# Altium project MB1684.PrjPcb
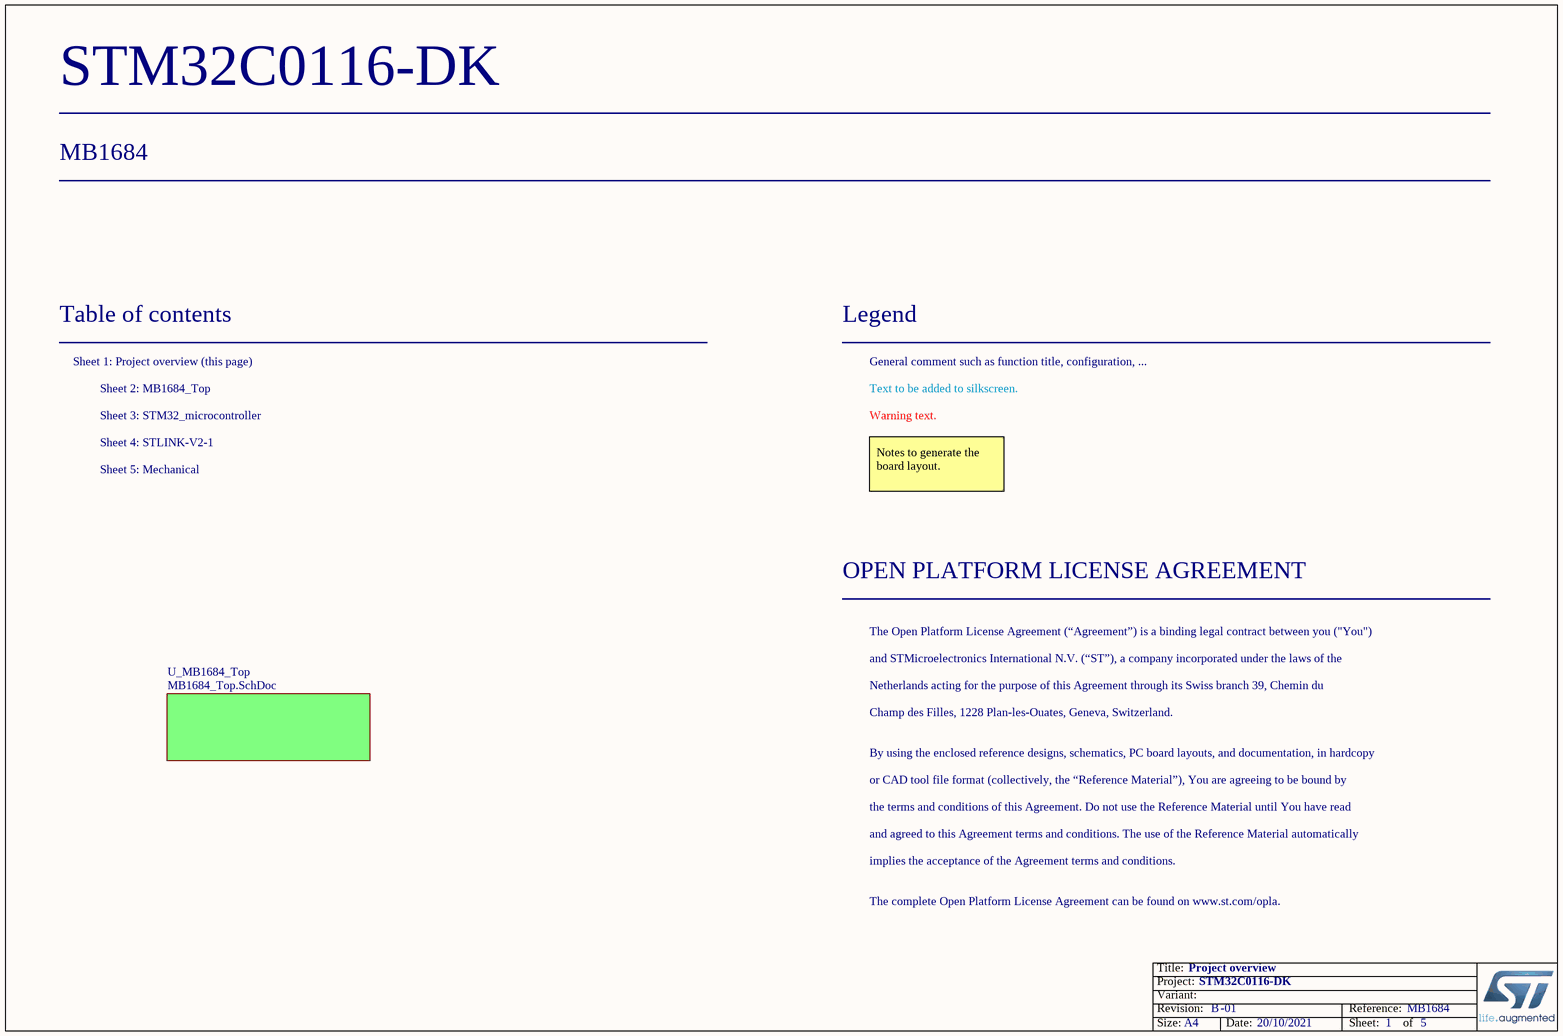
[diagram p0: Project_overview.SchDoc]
Board_Reference: MB1684; Board_PCB_Revision: B; Board_Name: STM32C0116-DK; Board_Document_Date: 20/10/2021; Board_Assembly_Revision: 01
5 sheets, 73 parts. Net scope: flat (ports and power ports of the same name join across sheets).
Board file: MB1684.PcbDoc
Sheets:
  Project_overview.SchDoc
    U_MB1684_Top = MB1684_Top.SchDoc
      U_STM32_microcontroller = STM32_microcontroller.SchDoc
      U_ST_LINK_V2_1 = ST_LINK_V2_1.SCHDOC
      U_Mechanical = Mechanical.SchDoc

## Sheet Project_overview.SchDoc: Project overview
size A4; Date: Not used; ApprovedBy: Not used; CheckedBy: Not used; Author: Not used; CompanyName: STMicroelectronics; DrawnBy: Not used; Engineer: Not used; Organization: Not used; Address1: Not used; Address2: Not used; Address3: Not used; Address4: Not used; DocumentNumber: Not used; Revision: Not used; SheetNumber: 1; SheetTotal: 5

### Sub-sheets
U_MB1684_Top = MB1684_Top.SchDoc: no entries

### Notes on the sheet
- Table of contents
- Sheet 1: Project overview (this page)
- Legend
- General comment such as function title, configuration, ...
- Sheet 2: MB1684_Top
- Sheet 4: STLINK-V2-1
- Sheet 3: STM32_microcontroller
- Text to be added to silkscreen.
- Warning text.
- Sheet 5: Mechanical
- Notes to generate the board layout.
- OPEN PLATFORM LICENSE AGREEMENT
- The Open Platform License Agreement (“Agreement”) is a binding legal contract between you ("You")
- and STMicroelectronics International N.V. (“ST”), a company incorporated under the laws of the
- Netherlands acting for the purpose of this Agreement through its Swiss branch 39, Chemin du
- Champ des Filles, 1228 Plan-les-Ouates, Geneva, Switzerland.
- By using the enclosed reference designs, schematics, PC board layouts, and documentation, in hardcopy
- or CAD tool file format (collectively, the “Reference Material”), You are agreeing to be bound by
- the terms and conditions of this Agreement. Do not use the Reference Material until You have read
- and agreed to this Agreement terms and conditions. The use of the Reference Material automatically
- implies the acceptance of the Agreement terms and conditions.
- The complete Open Platform License Agreement can be found on www.st.com/opla.

## Sheet MB1684_Top.SchDoc: Top hierarchical view
size A4; Date: Not used; ApprovedBy: Not used; CheckedBy: Not used; Author: Not used; CompanyName: STMicroelectronics; DrawnBy: Not used; Engineer: Not used; Organization: Not used; Address1: Not used; Address2: Not used; Address3: Not used; Address4: Not used; DocumentNumber: Not used; Revision: A-01-P3; SheetNumber: 2; SheetTotal: 5
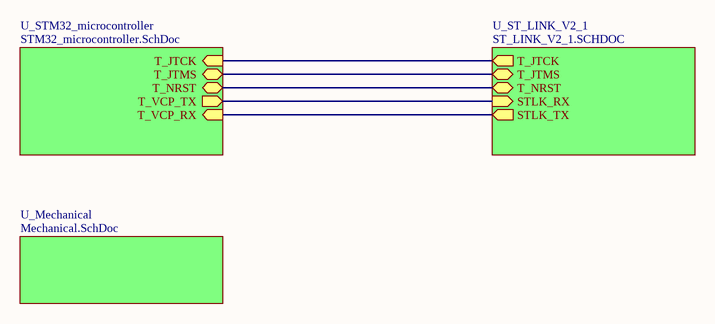
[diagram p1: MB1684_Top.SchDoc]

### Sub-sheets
U_Mechanical = Mechanical.SchDoc: no entries
U_ST_LINK_V2_1 = ST_LINK_V2_1.SCHDOC: T_JTMS (bidir), T_JTCK (out), T_NRST (bidir), STLK_RX (in), STLK_TX (out)
U_STM32_microcontroller = STM32_microcontroller.SchDoc: T_JTMS (bidir), T_NRST (bidir), T_JTCK (in), T_VCP_RX (in), T_VCP_TX (out)

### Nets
(unnamed): sheet U_STM32_microcontroller/T_JTMS, sheet U_ST_LINK_V2_1/T_JTMS
(unnamed): sheet U_STM32_microcontroller/T_NRST, sheet U_ST_LINK_V2_1/T_NRST  [a separate net that carries the same name]
(unnamed): sheet U_STM32_microcontroller/T_JTCK, sheet U_ST_LINK_V2_1/T_JTCK  [a separate net that carries the same name]
(unnamed): sheet U_STM32_microcontroller/T_VCP_RX, sheet U_ST_LINK_V2_1/STLK_TX  [a separate net that carries the same name]
(unnamed): sheet U_STM32_microcontroller/T_VCP_TX, sheet U_ST_LINK_V2_1/STLK_RX  [a separate net that carries the same name]

## Sheet STM32_microcontroller.SchDoc: MCU
size A4; CompanyName: STMicroelectronics; Organization: Microcontrollers Division; DocumentNumber: MCD16-037; Revision: A-01; SheetNumber: 3; SheetTotal: 5; Project: STM32L476 Brisk
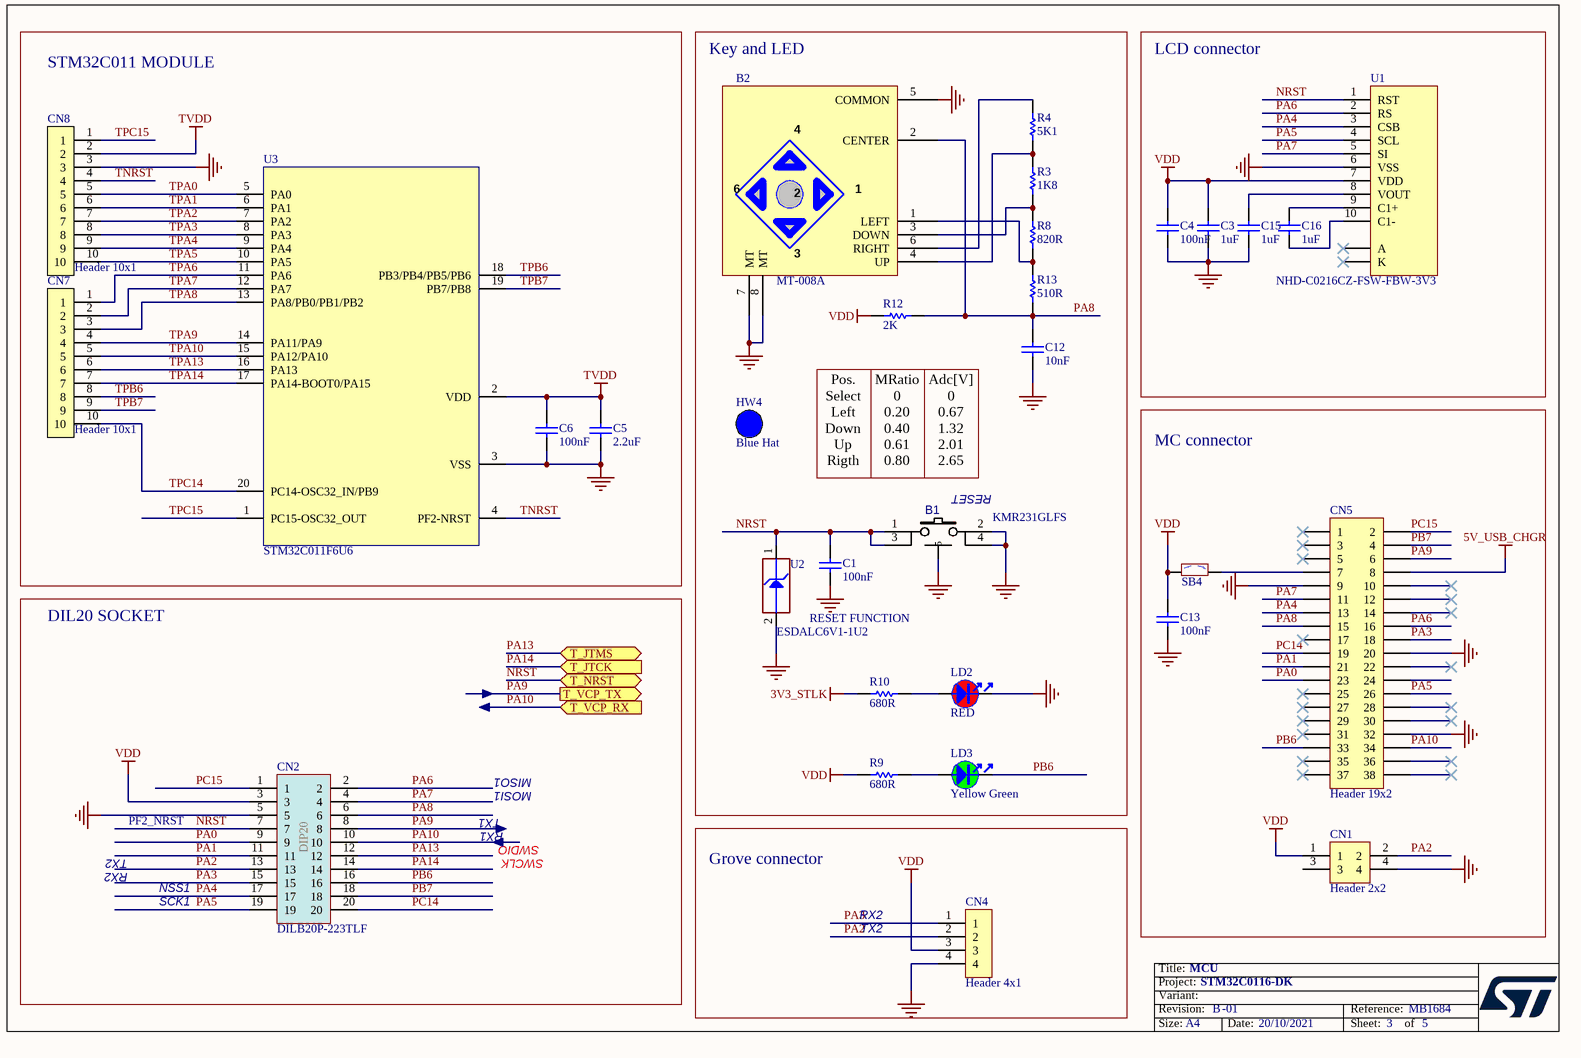
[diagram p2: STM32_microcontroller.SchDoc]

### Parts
B1  value KMR231GLFS  [SWI_C&K_Y78B23110FP__ITT_KMR231GLFS]  (hidden comment: SW-PUSH-CMS_KMR2_BLACK)
B2  value MT-008A  [SWI_XIEJIA_MT-008A_6P]  (hidden comment: Joystick MT-008A_M)
C1  value 100nF  [C0402]  (hidden comment: Capacitor)
C3  value 1uF  [C0603]  (hidden comment: Capacitor)
C4  value 100nF  [C0402]  (hidden comment: Capacitor)
C5  value 2.2uF  [C0603]  (hidden comment: Capacitor)
C6  value 100nF  [C0402]  (hidden comment: Capacitor)
C12  value 10nF  [C0402]  (hidden comment: Capacitor)
C13  value 100nF  [C0402]  (hidden comment: Capacitor)
C15  value 1uF  [C0603]  (hidden comment: Capacitor)
C16  value 1uF  [C0603]  (hidden comment: Capacitor)
CN1  Header 2x2  [CON_SAMTEC_TSW-102-09-G-D]
CN2  value DILB20P-223TLF  [CON_FCI_DILB20P-223TLF]  (hidden comment: Socket 10x2_DIP20)
CN4  Header 4x1  [CON_988-JIUBABA_A2006LF-04A]
CN5  Header 19x2  [CON_SAMTEC_TSW-119-09-X-D]
CN7  Header 10x1  [CON_SAMTEC_TSW-110-07-G-S]
CN8  Header 10x1  [CON_SAMTEC_TSW-110-07-G-S]
HW4  value Blue Hat  (hidden comment: BUTTON_HAT_BLUE)  (mechanical)
LD2  value RED  [LED_0402_KINGBRIGHT_KPHHS-1005SURCK_HYPER-RED_1A2K_H0P5]  (hidden comment: LED_red)
LD3  value Yellow Green  [LED_0402_EVERLIGHT_16-213SYGC/S530-E3-TR8 _YELLOW-GREEN_1A2K_H0P45]  (hidden comment: LED_green)
R3  value 1K8  [R0402]  (hidden comment: Resistor)
R4  value 5K1  [R0402]  (hidden comment: Resistor)
R8  value 820R  [R0402]  (hidden comment: Resistor)
R9  value 680R  [R0402]  (hidden comment: Resistor)
R10  value 680R  [R0402]  (hidden comment: Resistor)
R12  value 2K  [R0402]  (hidden comment: Resistor)
R13  value 510R  [R0402]  (hidden comment: Resistor)
SB4  SB_OFF  [SOLDER-BRIDGE_R0603-0R]  (value not drawn)
U1  NHD-C0216CZ-FSW-FBW-3V3  [LCD_NHD_C0216CZ_FSW_FBW_3V3]
U2  value ESDALC6V1-1U2  [ESD_ST0201]  (hidden comment: ESD-TRANSIL)
U3  STM32C011F6U6  [ICC_UFQFPN20_3X3_P050]

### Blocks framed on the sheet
STM32C011 MODULE: C5 C6 CN7 CN8 U3
Key and LED: B1 B2 C1 C12 HW4 LD2 LD3 R3 R4 R8-R10 R12 R13 U2
LCD connector: C3 C4 C15 C16 U1
MC connector: C13 CN1 CN5 SB4
DIL20 SOCKET: CN2
Grove connector: CN4

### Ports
T_JTCK (in), T_JTMS (bidir), T_NRST (bidir), T_VCP_RX (in), T_VCP_TX (out)

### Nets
3V3_STLK: R10.2
5V_USB_CHGR: CN5.8
GND: B1.2 B1.4 B1.5 B2.5(COMMON) B2.7(MT) B2.8(MT) C1.1 C3.1 C4.1 C12.1 C13.1 C15.1 CN1.4 CN2.5 CN4.4 CN5.9 CN5.20 CN5.32 LD2.2 U1.6(VSS) U2.2(GND)
TGND: C5.1 C6.1 CN8.3 U3.3(VSS)
TVDD: C5.2 C6.2 CN8.2 U3.2(VDD)
VDD: C3.2 C4.2 C13.2 CN1.1 CN2.3 CN4.3 R9.2 R12.1 SB4.1 U1.7(VDD)
NRST: B1.1 B1.3 C1.2 CN2.7 U1.1(RST) U2.1(IO1) ; port T_NRST
PA0: CN2.9 CN5.23
PA1: CN2.11 CN5.21
PA2: CN1.2 CN2.13 CN4.2
PA3: CN2.15 CN4.1 CN5.18
PA4: CN2.17 CN5.13 U1.3(CSB)
PA5: CN2.19 CN5.26 U1.4(SCL)
PA6: CN2.2 CN5.16 U1.2(RS)
PA7: CN2.4 CN5.11 U1.5(SI)
PA8: B2.2(CENTER) C12.2 CN2.6 CN5.15 R12.2 R13.1
PA9: CN2.8 CN5.6 ; port T_VCP_TX
PA10: CN2.10 CN5.34 ; port T_VCP_RX
PA13: CN2.12 ; port T_JTMS
PA14: CN2.14 ; port T_JTCK
PB6: CN2.16 CN5.33 LD3.2
PB7: CN2.18 CN5.4
PC14: CN2.20 CN5.19
PC15: CN2.1 CN5.2
TNRST: CN8.4 U3.4(PF2-NRST)
TPA0: CN8.5 U3.5(PA0)
TPA1: CN8.6 U3.6(PA1)
TPA2: CN8.7 U3.7(PA2)
TPA3: CN8.8 U3.8(PA3)
TPA4: CN8.9 U3.9(PA4)
TPA5: CN8.10 U3.10(PA5)
TPA6: CN7.1 U3.11(PA6)
TPA7: CN7.2 U3.12(PA7)
TPA8: CN7.3 U3.13(PA8/PB0/PB1/PB2)
TPA9: CN7.4 U3.14(PA11/PA9)
TPA10: CN7.5 U3.15(PA12/PA10)
TPA13: CN7.6 U3.16(PA13)
TPA14: CN7.7 U3.17(PA14-BOOT0/PA15)
TPB6: CN7.8 U3.18(PB3/PB4/PB5/PB6)
TPB7: CN7.9 U3.19(PB7/PB8)
TPC14: CN7.10 U3.20(PC14-OSC32_IN/PB9)
TPC15: CN8.1 U3.1(PC15-OSC32_OUT)
NetB2_1: B2.1(LEFT) R8.1 R13.2
NetB2_3: B2.3(DOWN) R3.1 R8.2
NetB2_4: B2.4(UP) R3.2 R4.1
NetB2_6: B2.6(RIGHT) R4.2
NetC15_2: C15.2 U1.8(VOUT)
NetC16_1: C16.1 U1.10(C1-)
NetC16_2: C16.2 U1.9(C1+)
NetCN5_7: CN5.7 SB4.2
NetLD2_1: LD2.1 R10.1
NetLD3_1: LD3.1 R9.1

Not connected (* = marked no-connect by the designer): CN1 3; CN5 1* 3* 5* 10* 12* 14* 17* 22* 24 25* 27* 28* 29* 30* 31* 35* 36* 37* 38*; U1 11(A)* 12(K)*

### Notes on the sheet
- Pos.
  Select
  Left
  Down
  Up
  Rigth
- MRatio
  0
  0.20
  0.40
  0.61
  0.80
- Adc[V]
  0
  0.67
  1.32
  2.01
  2.65
- (near B1) RESET
- RESET FUNCTION
- MOSI1
- MISO1
- PF2_NRST
- TX2
- TX1
- RX1
- SWDIO
- SWCLK
- RX2
- NSS1
- SCK1

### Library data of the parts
B1 = MCD-01485: Microminiature Tact Switch for SMT - KMR 2 Series - 1.9 mm height; Part_Type: Misc; Manufacturer: C&K; Part_Preference: Recommended; Provided_By: SUBCO; Component_Country_Of_Origin: France
B2 = MCD-00132: Joystick, 4 dir, 1 OK; BMS_Part_Number: 9180124; Part_Preference: Recommended; Part_Type: Misc; Manufacturer: XIEJIA ELECTRONICS; Component_Country_Of_Origin: Unknown
C1 C4 C6 C13 = MCD-00006: Capacitor, MLCC, 100nF, 16V, X7R, +/-10%, 0402, T=0.5mm; Manufacturer_Part_Number: CC0402KRX7R7BB104; Manufacturer: YAGEO; Alternate_Manufacturer_Part_Number: GCM155R71C104KA55D; Alternate_Manufacturer: MURATA; Part_Preference: Recommended; Provided_By: SUBCO; ECCN_US: EAR99; ECCN_EU: NEC; Order_Code_RS: 616-9701; Component_Country_Of_Origin: China
C3 C15 C16 = MCD-01100: Capacitor, MLCC, 1uF, 25V, X5R, +/-10%, 0603, T=0.8mm; Manufacturer_Part_Number: CC0603KRX5R8BB105; Manufacturer: YAGEO; Alternate_Manufacturer_Part_Number: GCM155R71C104KA55D; Alternate_Manufacturer: MURATA; BMS_Part_Number: 9142279; Part_Preference: Recommended; ECCN_US: EAR99; ECCN_EU: NEC; Provided_By: SUBCO; Component_Country_Of_Origin: China
C5 = MCD-00654: Capacitor, MLCC, 2.2uF, 16V, X5R, +/-10%, 0603, T=0.8mm; Manufacturer_Part_Number: CC0603KRX5R7BB225; Manufacturer: YAGEO; Alternate_Manufacturer_Part_Number: GCM155R71C104KA55D; Alternate_Manufacturer: MURATA; BMS_Part_Number: 9142001; Part_Preference: Recommended; ECCN_US: EAR99; ECCN_EU: NEC; Provided_By: SUBCO; Component_Country_Of_Origin: China
C12 = MCD-00011: Capacitor, MLCC, 10nF, 16V, X7R, +/-10%, 0402, T=0.5mm; Manufacturer_Part_Number: CC0402KRX7R7BB103; Manufacturer: YAGEO; Alternate_Manufacturer_Part_Number: GCM155R71C104KA55D; Alternate_Manufacturer: MURATA; Part_Preference: Recommended; Provided_By: SUBCO; ECCN_US: EAR99; ECCN_EU: NEC; Order_Code_RS: 669-8688; Component_Country_Of_Origin: China
CN1 = MCD-02440: Header, 2x2, 2.54mm, VR, TH, T=5.84mm/10.16mm; Part_Type: Connector; Part_Preference: Recommended; Manufacturer: SAMTEC; Manufacturer_Part_Number: TSW-102-09-G-D; Component_Country_Of_Origin: China, Costa Rica, Malaysia, United States, Vietnam
CN2 = MCD-02204: Socket_IC, 20 (2 x 10) Pos DIP, 0.3" (7.62mm) Row Spacing Socket Tin Through Hole; Part_Preference: Recommended; Manufacturer: AMPHENOL ICC; Component_Country_Of_Origin: Taiwan
CN4 = MCD-01741: Header, 4x1, 2mm, VR, SMD; Part_Type: Connector; Manufacturer_Part_Number: A2006LF-04A; Manufacturer: JIUBABA; Part_Preference: Alternate; Component_Country_Of_Origin: Unknown; Alternate_EMS: A
CN5 = MCD-00213: Header, 19x2, 2.54mm, VR, TH, T=5.84mm/10.16mm; Manufacturer_Part_Number: TSW-119-09-G-D; Manufacturer: SAMTEC; Part_Type: Connector; Part_Preference: Recommended; Provided_By: SUBCO; Component_Country_Of_Origin: China, Costa Rica, Malaysia, United States, Vietnam
CN7 CN8 = MCD-02708: Header, 10x1, 2.54mm, VR, TH, T=5.84mm/2.54mm; Part_Type: Connector; Part_Preference: Recommended; Manufacturer: SAMTEC; Manufacturer_Part_Number: TSW-110-07-G-S
HW4 = MCD-02136: Switch hat, blue, For KTSC-62B; Part_Type: Misc; Part_Preference: Recommended; Manufacturer: APEM INC; Manufacturer_Part_Number: AKTSC62B; Order_Code_RS: 378-6779; Component_Country_Of_Origin: Unknown
LD2 = MCD-00708: LED 0402 Red; Part_Type: Display; Manufacturer_Part_Number: KPHHS-1005SURCK; Manufacturer: KINGBRIGHT; Alternate_Manufacturer_Part_Number: LS Q976-NR-1; Alternate_Manufacturer: OSRAM OPTO SEMICONDUCTORS; Part_Preference: Recommended; Provided_By: SUBCO; Component_Country_Of_Origin: Unknown
LD3 = MCD-02330: LED, Yellow Green, 2V, 25mA, 0402, 0.45mm; Part_Type: Display; Manufacturer_Part_Number: 16-213SYGC/S530-E3/TR8; Manufacturer: EVERLIGHT; Alternate_Manufacturer_Part_Number: LG Q396-PS-35; Alternate_Manufacturer: OSRAM OPTO SEMICONDUCTORS; Part_Preference: Recommended; Provided_By: SUBCO; Component_Country_Of_Origin: China
R3 = MCD-00409: Resistor, 1K8, 0402, +/-1%, 1/16W; Manufacturer_Part_Number: RC0402FR-071K8L; Manufacturer: YAGEO; Alternate_Manufacturer_Part_Number: RT0402FRE07100KL; Part_Preference: Recommended; ECCN_US: EAR99; ECCN_EU: NEC; Provided_By: SUBCO; Component_Country_Of_Origin: China
R4 = MCD-00333: Resistor, 5K1, 0402, +/-1%, 1/16W; Manufacturer_Part_Number: RC0402FR-075K1L; Manufacturer: YAGEO; Alternate_Manufacturer_Part_Number: RT0402FRE07100KL; Part_Preference: Recommended; ECCN_US: EAR99; ECCN_EU: NEC; Provided_By: SUBCO; Component_Country_Of_Origin: China
R8 = MCD-00527: Resistor, 820R, 0402, +/-1%, 1/16W; Manufacturer_Part_Number: RC0402FR-07820RL; Manufacturer: YAGEO; Alternate_Manufacturer_Part_Number: RT0402FRE07100KL; Part_Preference: Recommended; ECCN_US: EAR99; ECCN_EU: NEC; Provided_By: SUBCO; Component_Country_Of_Origin: China
R9 R10 = MCD-00507: Resistor, 680R, 0402, +/-1%, 1/16W; Manufacturer_Part_Number: RC0402FR-07680RL; Manufacturer: YAGEO; Alternate_Manufacturer_Part_Number: RT0402FRE07100KL; Part_Preference: Recommended; ECCN_US: EAR99; ECCN_EU: NEC; Provided_By: SUBCO; Component_Country_Of_Origin: China
R12 = MCD-00419: Resistor, 2K, 0402, +/-1%, 1/16W; Manufacturer_Part_Number: RC0402FR-072KL; Manufacturer: YAGEO; Alternate_Manufacturer_Part_Number: RT0402FRE07100KL; Part_Preference: Recommended; ECCN_US: EAR99; ECCN_EU: NEC; Provided_By: SUBCO; Component_Country_Of_Origin: China
R13 = MCD-00064: Resistor, 510R, 0402, +/-1%, 1/16W; Manufacturer_Part_Number: RC0402FR-07510RL; Manufacturer: YAGEO; Alternate_Manufacturer_Part_Number: RT0402FRE07100KL; Part_Preference: Recommended; ECCN_US: EAR99; ECCN_EU: NEC; Provided_By: SUBCO; Component_Country_Of_Origin: China
SB4 = MCD-00072: Solder Bridge OFF; Part_Type: Misc; Manufacturer_Part_Number: RC0603JR-070RL; Manufacturer: YAGEO; Part_Preference: Recommended; Component_Country_Of_Origin: China
U1 = MCD-02205: Character LCD Display Module Transflective 5 x 8 Dots FSTN - Film Super-Twisted Nematic LED - White Serial; Part_Preference: Recommended; Manufacturer: NEWHAVEN DISPLAY INTL; Component_Country_Of_Origin: China
U2 = MCD-00170: ESD protection 6V1; Part_Type: Diode; Manufacturer: STMICROELECTRONICS; BMS_Part_Number: 9151132; Part_Preference: Recommended; Manufacturer_HQ_COO: EU; Provided_By: SUBCO with ST control; ECCN_US: EAR99; ECCN_EU: NEC; Component_Country_Of_Origin: China
U3 = MCD-02313: MCU, ARM™-based 32-bit MCU Cortex-M0+, 32KB Flash, 6KB SRAM; Part_Type: IC; Part_Preference: Recommended; Manufacturer: STMICROELECTRONICS; Component_Country_Of_Origin: Unknown

## Sheet ST_LINK_V2_1.SCHDOC: ST-LINK/V2 SWD mode
size A4; CompanyName: STMicroelectronics; Organization: Microcontrollers Division; SheetNumber: 4; SheetTotal: 5
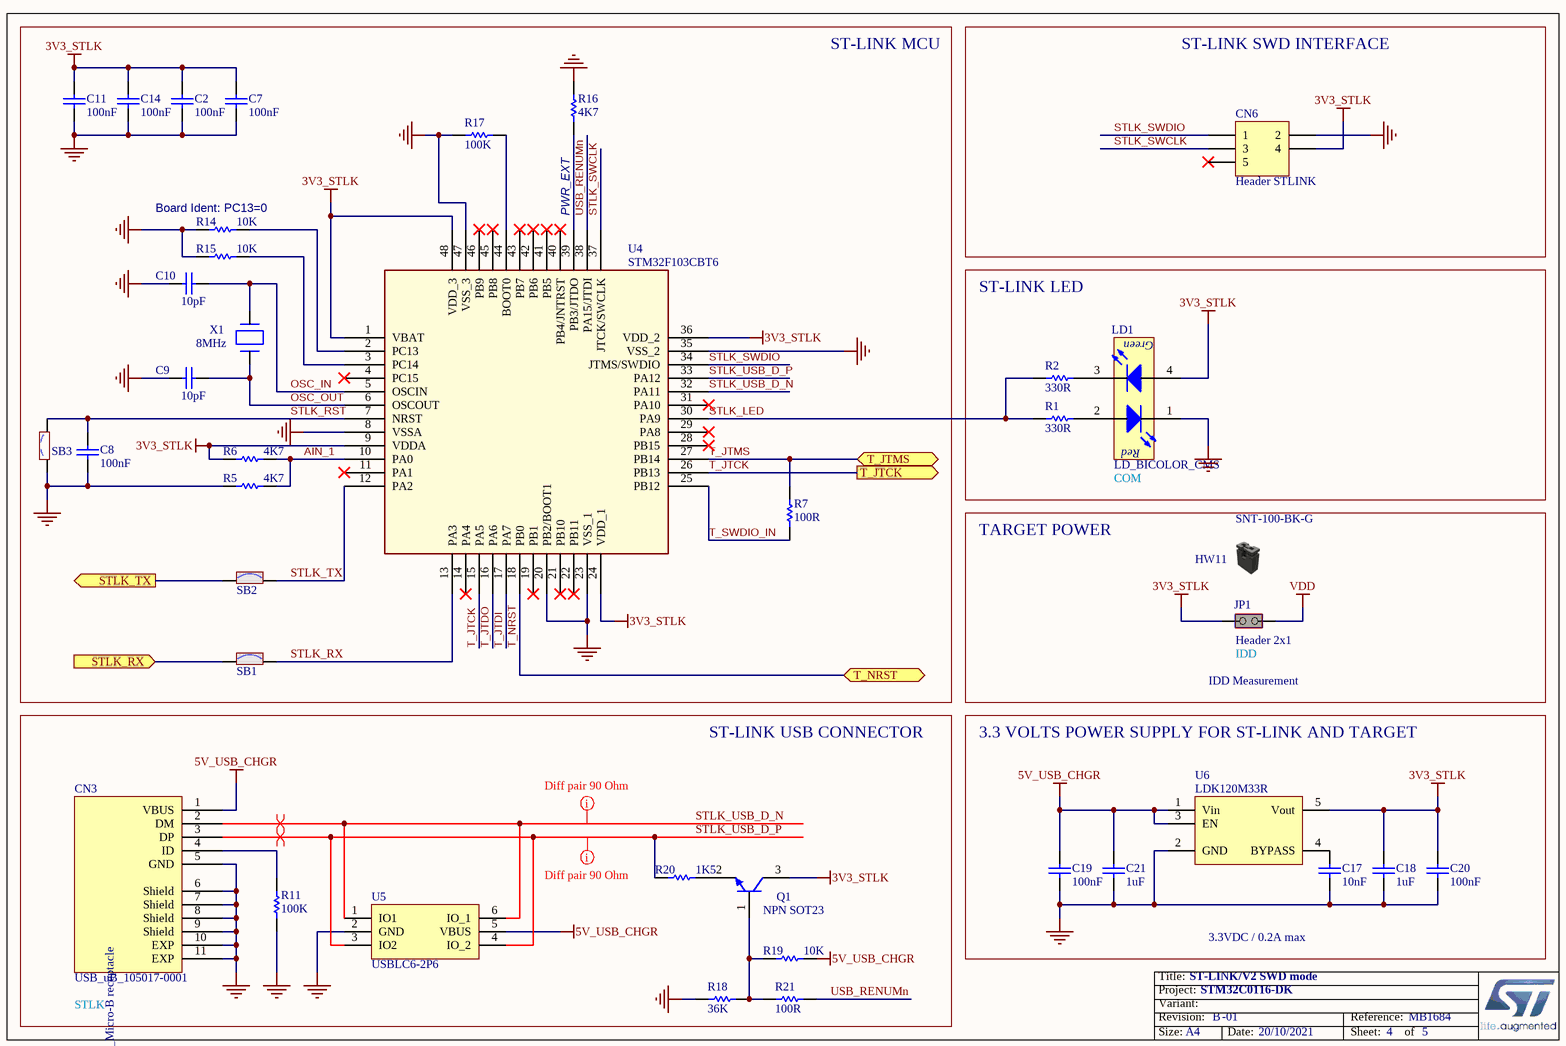
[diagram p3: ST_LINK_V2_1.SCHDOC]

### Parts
C2  value 100nF  [C0402]  (hidden comment: Capacitor)
C7  value 100nF  [C0402]  (hidden comment: Capacitor)
C8  value 100nF  [C0402]  (hidden comment: Capacitor)
C9  value 10pF  [C0402]  (hidden comment: Capacitor)
C10  value 10pF  [C0402]  (hidden comment: Capacitor)
C11  value 100nF  [C0402]  (hidden comment: Capacitor)
C14  value 100nF  [C0402]  (hidden comment: Capacitor)
C17  value 10nF  [C0402]  (hidden comment: Capacitor)
C18  value 1uF  [C0402]  (hidden comment: Capacitor)
C19  value 100nF  [C0402]  (hidden comment: Capacitor)
C20  value 100nF  [C0402]  (hidden comment: Capacitor)
C21  value 1uF  [C0402]  (hidden comment: Capacitor)
CN3  value USB_uB_105017-0001  [CON_USBMICROB_MOLEX_105017-0001_H2P90]  (hidden comment: USB_uB_105017.0001)
CN6  Header STLINK  [HDR_1x5_2R54_V_M]
HW11  value SNT-100-BK-G  (hidden comment: Shunt Black 2.54mm)  (mechanical)
JP1  value Header 2x1  [CON_SAMTEC_TSW-102-07-G-S]  (hidden comment: Jumper_Header 2x1 Fitted)
LD1  LD_BICOLOR_CMS  [LED_BI-GR_HSMF-A201-A00J1]
Q1  value NPN SOT23  [NPN_SOT23]  (hidden comment: 9013-SOT23)
R1  value 330R  [R0402]  (hidden comment: Resistor)
R2  value 330R  [R0402]  (hidden comment: Resistor)
R5  value 4K7  [R0402]  (hidden comment: Resistor)
R6  value 4K7  [R0402]  (hidden comment: Resistor)
R7  value 100R  [R0402]  (hidden comment: Resistor)
R11  value 100K  [R0402]  (hidden comment: Resistor)
R14  value 10K  [R0402]  (hidden comment: Resistor)
R15  value 10K  [R0402]  (hidden comment: Resistor)
R16  value 4K7  [R0402]  (hidden comment: Resistor)
R17  value 100K  [R0402]  (hidden comment: Resistor)
R18  value 36K  [R0402]  (hidden comment: Resistor)
R19  value 10K  [R0402]  (hidden comment: Resistor)
R20  value 1K5  [R0402]  (hidden comment: Resistor)
R21  value 100R  [R0402]  (hidden comment: Resistor)
SB1  SB_ON  [SOLDER-BRIDGE_R0402-0R]  (value not drawn)
SB2  SB_ON  [SOLDER-BRIDGE_R0402-0R]  (value not drawn)
SB3  SB_OFF  [SOLDER-BRIDGE_R0603-0R]  (value not drawn)
U4  STM32F103CBT6  [ICC_LQFP48_7X7_P050]
U5  USBLC6-2P6  [ESD_SOT666]
U6  LDK120M33R  [REG_SOT23-5L]
X1  value 8MHz  [CRY_NX3225GD_2P]  (hidden comment: XTAL_2_PINS)

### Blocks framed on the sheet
ST-LINK MCU: C2 C7-C11 C14 R5-R7 R14-R17 SB1-SB3 U4 X1
ST-LINK SWD INTERFACE: CN6
ST-LINK LED: LD1 R1 R2
TARGET POWER: HW11 JP1
ST-LINK USB CONNECTOR: CN3 Q1 R11 R18-R21 U5
3.3 VOLTS POWER SUPPLY FOR ST-LINK AND TARGET: C17-C21 U6

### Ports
STLK_RX (in), STLK_TX (out), T_JTCK (out), T_JTMS (bidir), T_NRST (bidir)

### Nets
3V3_STLK: C2.2 C7.2 C11.2 C14.2 C18.2 C20.2 CN6.4 JP1.1(COMMON) LD1.4(YellowGreen_anode) Q1.3(C) R6.1 U4.1(VBAT) U4.9(VDDA) U4.24(VDD_1) U4.36(VDD_2) U4.48(VDD_3) U6.5(Vout)
5V_USB_CHGR: C19.2 C21.2 CN3.1(VBUS) R19.2 U5.5(VBUS) U6.1(Vin) U6.3(EN)
GND: C2.1 C7.1 C8.1 C9.1 C10.1 C11.1 C14.1 C17.1 C18.1 C19.1 C20.1 C21.1 CN3.5(GND) CN3.6(Shield) CN3.7(Shield) CN3.8(Shield) CN3.9(Shield) CN3.10(EXP) CN3.11(EXP) CN6.2 LD1.1(RED_cathode) R5.1 R11.1 R14.1 R15.1 R16.2 R17.1 R18.1 SB3.1 U4.8(VSSA) U4.20(PB2/BOOT1) U4.23(VSS_1) U4.35(VSS_2) U4.47(VSS_3) U5.2(GND) U6.2(GND)
VDD: JP1.2(NO)
AIN_1: R5.2 R6.2 U4.10(PA0)
OSC_IN: C10.2 U4.5(OSCIN) X1.1(X1)
OSC_OUT: C9.2 U4.6(OSCOUT) X1.2(X2)
STLK_LED: R1.1 R2.1 U4.30(PA9)
STLK_RST: C8.2 SB3.2 U4.7(NRST)
STLK_RX: SB1.2 U4.13(PA3)
STLK_SWCLK: CN6.3 U4.37(JTCK/SWCLK)
STLK_SWDIO: CN6.1 U4.34(JTMS/SWDIO)
STLK_TX: SB2.2 U4.12(PA2)
STLK_USB_D_N: CN3.2(DM) U4.32(PA11) U5.1(IO1) U5.6(IO_1)
STLK_USB_D_P: CN3.3(DP) R20.1 U4.33(PA12) U5.3(IO2) U5.4(IO_2)
T_JTCK: U4.15(PA5) U4.26(PB13) ; port T_JTCK  [project net PA14]
T_JTDI: U4.17(PA7)
T_JTDO: U4.16(PA6)
T_JTMS: R7.2 U4.27(PB14) ; port T_JTMS  [project net PA13]
T_NRST: U4.18(PB0) ; port T_NRST  [project net NRST]
T_SWDIO_IN: R7.1 U4.25(PB12)
USB_RENUMn: R21.2 U4.38(PA15/JTDI)
NetC17_2: C17.2 U6.4(BYPASS)
NetCN3_4: CN3.4(ID) R11.2
NetLD1_2: LD1.2(Red_anode) R1.2
NetLD1_3: LD1.3(YellowGreen_cathode) R2.2
NetQ1_1: Q1.1(B) R18.2 R19.1 R21.1
NetQ1_2: Q1.2(E) R20.2
NetR14_2: R14.2 U4.2(PC13)
NetR15_2: R15.2 U4.3(PC14)
NetR16_1: R16.1 U4.39(PB3/JTDO)
NetR17_2: R17.2 U4.44(BOOT0)
NetSB1_1: SB1.1 ; port STLK_RX
NetSB2_1: SB2.1 ; port STLK_TX

Not connected (* = marked no-connect by the designer): CN6 5*; U4 4(PC15)* 11(PA1)* 14(PA4)* 19(PB1)* 21(PB10)* 22(PB11)* 28(PB15)* 29(PA8)* 31(PA10)* 40(PB4/JNTRST)* 41(PB5)* 42(PB6)* 43(PB7)* 45(PB8)* 46(PB9)*

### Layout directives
differential pair: STLK_USB_D_N, STLK_USB_D_P
mark named Diff pair 90 Ohm: STLK_USB_D_N, STLK_USB_D_P

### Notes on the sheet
- (near R14) Board Ident: PC13=0
- PWR_EXT
- COM
- (near JP1) IDD
- IDD Measurement
- 3.3VDC / 0.2A max
- STLK

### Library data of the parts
C2 C7 C8 C11 C14 C19 C20 = MCD-00006: as C1 on sheet STM32_microcontroller
C9 C10 = MCD-00015: Capacitor, MLCC, 10pF, 50V, NPO, +/-5%, 0402, T=0.5mm; Manufacturer_Part_Number: CC0402JRNPO9BN100; Manufacturer: YAGEO; Alternate_Manufacturer_Part_Number: GCM155R71C104KA55D; Alternate_Manufacturer: MURATA; Part_Preference: Recommended; Provided_By: SUBCO; ECCN_US: EAR99; ECCN_EU: NEC; Order_Code_RS: 616-9256; Component_Country_Of_Origin: China
C17 = MCD-00011: as C12 on sheet STM32_microcontroller
C18 C21 = MCD-00095: Capacitor, MLCC, 1uF, 25V, X5R, +/-10%, 0402, T=0.5mm; Manufacturer_Part_Number: GRM155R61E105KA12; Manufacturer: MURATA; Alternate_Manufacturer_Part_Number: GCM155R71C104KA55D; Part_Preference: Recommended; Provided_By: SUBCO; ECCN_US: EAR99; ECCN_EU: NEC; Order_Code_RS: 846-7287; Component_Country_Of_Origin: Japan
CN3 = MCD-00028: MicroUSB_TypeB, 5pins, 0.65mm, RA, SMD, T=2.9mm; Part_Type: Connector; Manufacturer_Part_Number: 1050170001; Manufacturer: MOLEX; Part_Preference: Recommended; Provided_By: SUBCO; Order_Code_RS: 848-6764; Component_Country_Of_Origin: Unknown
CN6 = Header STLINK: Header 5 pads for ST-LINK prog. Not fitted; Internal_Part_Number: MCD-01399; Part_Type: Mechanical; Provided_By: SUBCO; Initial_Board_Reference: MB1442
HW11 = MCD-00043: SHUNT 2.54mm BLACK; Manufacturer: SAMTEC; Part_Type: Misc; Part_Preference: Recommended; Alternate_Internal_Part_Number: MCD-02388; Component_Country_Of_Origin: China, Costa Rica, Malaysia, United States, Vietnam
JP1 = MCD-00683: Header, 2x1, 2.54mm, VR, TH, T=5.84mm/2.54mm; Part_Type: Connector; Manufacturer_Part_Number: TSW-102-07-G-S; Manufacturer: SAMTEC; Alternate_Manufacturer_Part_Number: 313102S111116; Alternate_Manufacturer: LIANYI; Part_Preference: Recommended; Alternate_Internal_Part_Number: MCD-02389; Provided_By: SUBCO; Order_Code_RS: 155-5312; Component_Country_Of_Origin: China, Costa Rica, Malaysia, United States, Vietnam
LD1 = MCD-02402: LED Bicolor; Part_Type: Display; Manufacturer_Part_Number: 67-22sursygc-s530-a2-tr8; Manufacturer: EVERLIGHT; Alternate_Manufacturer_Part_Number: LE-RGW35280; Alternate_Manufacturer: EVERLUCK; Part_Preference: Alternate; Alternate_Internal_Part_Number: MCD-00051; ECCN_US: EAR99; ECCN_EU: NEC; Provided_By: SUBCO; Alternate_EMS: C
Q1 = MCD-00073: NPN Bipolar Transistor; Part_Type: IC; Manufacturer_Part_Number: BSR14; Manufacturer: ON SEMICONDUCTOR; Part_Preference: Recommended; ECCN_US: EAR99; ECCN_EU: NEC; Provided_By: Subcon; Initial_Board_Reference: mb1274; Component_Country_Of_Origin: Unknown
R1 R2 = MCD-00062: Resistor, 330R, 0402, +/-1%, 1/16W; Manufacturer_Part_Number: RC0402FR-07330RL; Manufacturer: YAGEO; Alternate_Manufacturer_Part_Number: RT0402FRE07100KL; Part_Preference: Recommended; Provided_By: SUBCO; ECCN_US: EAR99; ECCN_EU: NEC; Component_Country_Of_Origin: China
R5 R6 R16 = MCD-00065: Resistor, 4K7, 0402, +/-1%, 1/16W; Manufacturer_Part_Number: RC0402FR-074K7L; Manufacturer: YAGEO; Alternate_Manufacturer_Part_Number: RT0402FRE07100KL; Part_Preference: Recommended; Provided_By: SUBCO; ECCN_US: EAR99; ECCN_EU: NEC; Component_Country_Of_Origin: China
R7 R21 = MCD-00067: Resistor, 100R, 0402, +/- 1%, 1/16W; Manufacturer_Part_Number: RC0402FR-07100RL; Manufacturer: YAGEO; Alternate_Manufacturer_Part_Number: RT0402FRE07100KL; Part_Preference: Recommended; Provided_By: SUBCO; ECCN_US: EAR99; ECCN_EU: NEC; Component_Country_Of_Origin: China
R11 R17 = MCD-00059: Resistor, 100K, 0402, +/-1%, 1/16W; Manufacturer_Part_Number: RC0402FR-07100KL; Manufacturer: YAGEO; Alternate_Manufacturer_Part_Number: RT0402FRE07100KL; Part_Preference: Recommended; Provided_By: SUBCO; ECCN_US: EAR99; ECCN_EU: NEC; Component_Country_Of_Origin: China
R14 R15 R19 = MCD-00053: Resistor, 10K, 0402, +/-1%, 1/16W; Manufacturer_Part_Number: RC0402FR-0710KL; Manufacturer: YAGEO; Alternate_Manufacturer_Part_Number: RT0402FRE07100KL; BMS_Part_Number: 9131590; Part_Preference: Recommended; Provided_By: SUBCO; ECCN_US: EAR99; ECCN_EU: NEC; Component_Country_Of_Origin: China
R18 = MCD-00069: Resistor, 36K, 0402, +/-1%, 1/16W; Manufacturer_Part_Number: RC0402FR-0736KL; Manufacturer: YAGEO; Alternate_Manufacturer_Part_Number: RT0402FRE07100KL; Part_Preference: Recommended; Provided_By: SUBCO; ECCN_US: EAR99; ECCN_EU: NEC; Component_Country_Of_Origin: China
R20 = MCD-00068: Resistor, 1K5, 0402, +/-1%, 1/16W; Manufacturer_Part_Number: RC0402FR-071K5L; Manufacturer: YAGEO; Alternate_Manufacturer_Part_Number: RT0402FRE07100KL; Part_Preference: Recommended; Provided_By: SUBCO; ECCN_US: EAR99; ECCN_EU: NEC; Component_Country_Of_Origin: China
SB1 SB2 = MCD-01618: Solder Bridge 0402 ON; Part_Type: Misc; Manufacturer_Part_Number: RC0402JR-070RL; Manufacturer: YAGEO; Part_Preference: Recommended; Provided_By: SUBCO; Order_Code_RS: 618-5804; Component_Country_Of_Origin: China
SB3 = MCD-00072: as SB4 on sheet STM32_microcontroller
U4 = MCD-00085: Medium-density performance line ARM-based 32-bit MCU with 128KB Flash; Manufacturer: STMICROELECTRONICS; Part_Type: IC; BMS_Part_Number: 9175111; Part_Preference: Recommended; Manufacturer_HQ_COO: EU; ECCN_US: 3A991A2; ECCN_EU: NEC; Provided_By: SUBCO with ST control; Component_Country_Of_Origin: Malaysia
U5 = MCD-00169: USB OTG FS ESD protection; Part_Type: IC; Manufacturer: STMICROELECTRONICS; BMS_Part_Number: 9151057; Part_Preference: Recommended; Manufacturer_HQ_COO: EU; Component_Country_Of_Origin: China
U6 = MCD-00663: 200 mA low quiescent current very low noise LDO; Part_Type: IC; Manufacturer: STMICROELECTRONICS; BMS_Part_Number: 9176330; Part_Preference: Recommended; Manufacturer_HQ_COO: EU; Component_Country_Of_Origin: China
X1 = MCD-00092: Crystal, 8MHz, 8pF, +/-20ppm, 500R, 3.2x2.5mm; Part_Type: Crystal_Osc; Manufacturer_Part_Number: NX3225GD-8MHZ-EXS00A-CG04874; Manufacturer: NDK; BMS_Part_Number: 9157029; Part_Preference: Recommended; ECCN_US: EAR99; ECCN_EU: NEC; Provided_By: SUBCO; Component_Country_Of_Origin: Unknown

## Sheet Mechanical.SchDoc: HW Mechanical parts
size A4; SheetNumber: 5; SheetTotal: 5
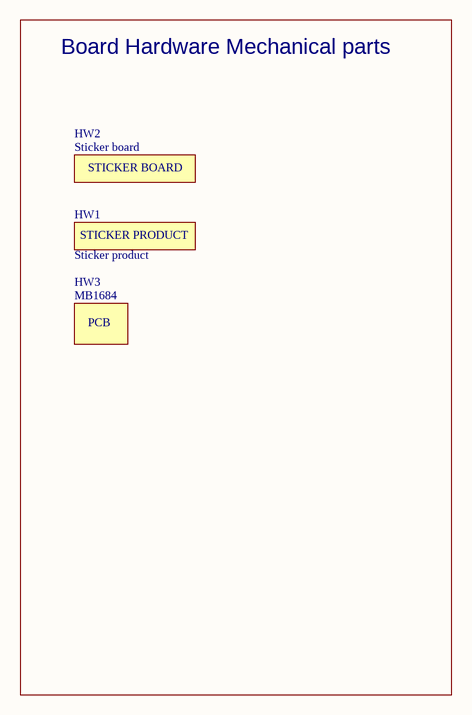
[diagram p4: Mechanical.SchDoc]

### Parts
HW1  value Sticker product  [STICKER_PRODUCT_15X5]  (hidden comment: STICKER_PRODUCT)  (no BOM)
HW2  value Sticker board  [STICKER_Board_15X5]  (hidden comment: STICKER_BOARD)  (no BOM)
HW3  value MB1684  (hidden comment: PCB)  (mechanical)

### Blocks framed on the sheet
Board Hardware Mechanical parts: HW1-HW3

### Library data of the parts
HW1 = MCD-02191: Sticker product 15x5 mm; Part_Type: Misc; Part_Preference: Recommended
HW2 = MCD-02192: Sticker board 15x5 mm; Part_Type: Misc; Part_Preference: Recommended
HW3 = MCD-02489: MB1684 PCB; Part_Preference: Recommended; Provided_By: SUBCO

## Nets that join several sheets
3V3_STLK: STM32_microcontroller (R10.2), ST_LINK_V2_1 (17 pins)
5V_USB_CHGR: STM32_microcontroller (CN5.8), ST_LINK_V2_1 (7 pins)
GND: STM32_microcontroller (21 pins), ST_LINK_V2_1 (36 pins)
VDD: STM32_microcontroller (10 pins), ST_LINK_V2_1 (JP1.2)
NRST: STM32_microcontroller (6 pins), ST_LINK_V2_1 (U4.18)
PA13: STM32_microcontroller (CN2.12), ST_LINK_V2_1 (R7.2 U4.27)
PA14: STM32_microcontroller (CN2.14), ST_LINK_V2_1 (U4.15 U4.26)

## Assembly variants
C011F6: not fitted C20 CN2 CN5 CN7 LD2 R10 R12 SB1 SB2 U5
